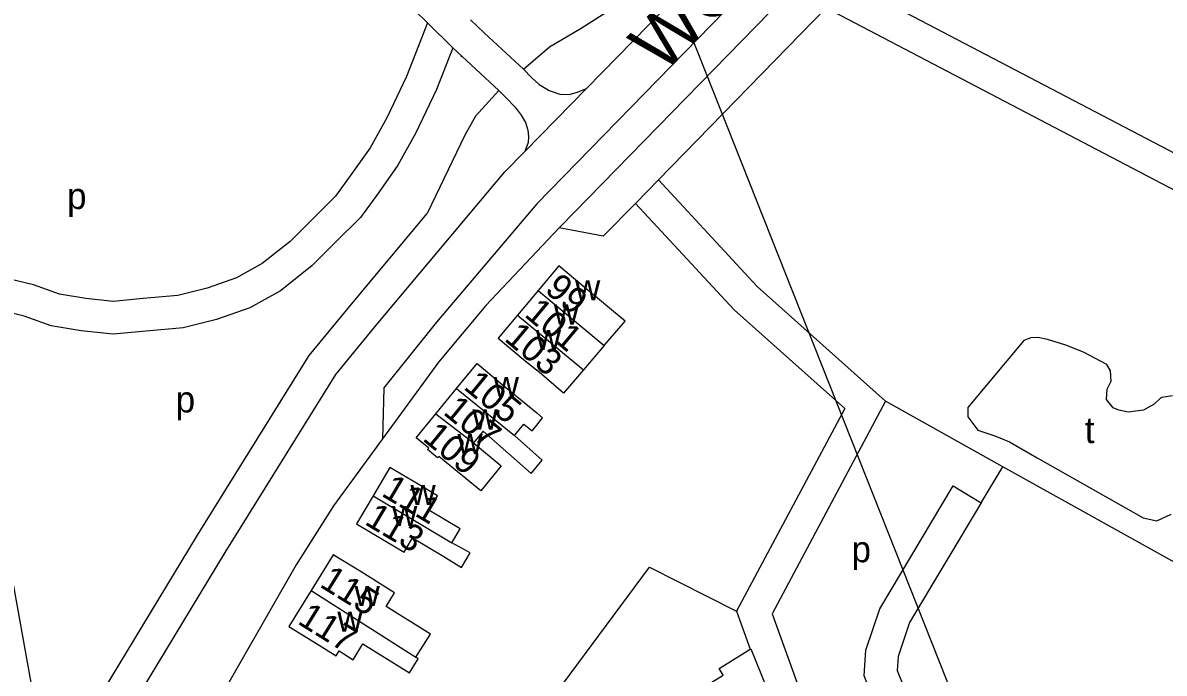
# Model space of a CAD drawing. Extents: x 162883 to 165538, y 383986 to 385172.
# Drawn here: x 164421.3 to 164596.1, y 384862.4 to 384962 of the extents above; entities that cross this region are included whole.
import ezdxf

# ---------------------------------------------------------------- set-up
doc = ezdxf.new("R2010")
doc.units = 0
for name, color, linetype in [('BLT_Basislijn', 7, 'Continuous'), ('BLT_Bebouwing', 7, 'Continuous'), ('BLT_Centroide', 7, 'Continuous'), ('BLT_Hoogspanningsmast_en_leidingen', 7, 'Continuous'), ('BLT_Huisnummer', 7, 'Continuous'), ('BLT_Huisnummer_ tussenligend', 7, 'Continuous'), ('BLT_Onderverdeling_panden', 7, 'Continuous'), ('BLT_Straatnaam_hoofdweg', 7, 'Continuous'), ('BLT_Vlakafsluiter', 7, 'Continuous')]:
    doc.layers.add(name, color=color, linetype=linetype)

msp = doc.modelspace()

# ---------------------------------------------------------------- linework, layer by layer
at = {"layer": 'BLT_Basislijn'}
for p, q in [((164589.79, 385026.4), (164500.03, 384934.28)), ((164578.81, 385007.97), (164503.61, 384930.79)), ((164548, 384968.08), (164658.3, 384910.3)), ((164544.36, 384964.34), (164518.64, 384937.96)), ((164544.36, 384964.34), (164663.27, 384902.05)), ((164491.99, 384960.42), (164497.99, 384954.91)), ((164487.17, 384958.19), (164494.22, 384951.67)), ((164518.64, 384937.96), (164515.14, 384934.37)), ((164503.46, 384930.63), (164492.22, 384918.72)), ((164503.61, 384930.79), (164503.46, 384930.63)), ((164571.42, 384894.04), (164553.46, 384904.05)), ((164568.11, 384888.51), (164571.42, 384894.04)), ((164622.91, 384865.35), (164571.42, 384894.04)), ((164530.6, 384871.89), (164532.71, 384866.07))]:
    msp.add_line(p, q, dxfattribs=at)
for points in [[(164507.61, 384951.95), (164526.58, 384971.35), (164580.15, 385026.28)], [(164458.77, 384969.91), (164466.55, 384971.29), (164470.08, 384971.61), (164472.32, 384971.29), (164474.57, 384970.16), (164477.3, 384967.91), (164483.29, 384962)], [(164497.99, 384954.91), (164501.95, 384958.33), (164506.81, 384961.21), (164515.23, 384966.64)], [(164483.29, 384962), (164480.07, 384953.82), (164477.02, 384947.49), (164474.49, 384942.87), (164471.7, 384938.93), (164469.19, 384935.5), (164465.49, 384931.79), (164462.23, 384928.54), (164457.95, 384925.16), (164454, 384922.96), (164449.51, 384921.39), (164445.02, 384920.26), (164439.68, 384919.8), (164435.13, 384919.34), (164430.9, 384919.79), (164426.87, 384920.46), (164422.89, 384921.87), (164418.02, 384923.08)], [(164483.29, 384962), (164487.17, 384958.19)], [(164489.87, 384962.5), (164491.99, 384960.42)], [(164487.17, 384958.19), (164484.66, 384951.82), (164481.47, 384945.2), (164478.73, 384940.22), (164475.76, 384936.01), (164473, 384932.23), (164469.02, 384928.26), (164465.56, 384924.8), (164460.73, 384920.98), (164456.05, 384918.38), (164450.95, 384916.59), (164445.85, 384915.32), (164440.15, 384914.82), (164435.11, 384914.32), (164430.23, 384914.83), (164425.62, 384915.6), (164421.45, 384917.07), (164416.73, 384918.25)], [(164488.38, 384956.99), (164488.51, 384956.86)], [(164497.99, 384954.91), (164499.22, 384953.63), (164500.37, 384952.59), (164501.9, 384951.66), (164503.54, 384951.12), (164504.96, 384951.06), (164506.27, 384951.39), (164507.61, 384951.95)], [(164494.22, 384951.67), (164490.62, 384947.71), (164489, 384944.83), (164483.24, 384932.8)], [(164494.22, 384951.67), (164495.34, 384950.52), (164496.71, 384949.1), (164497.64, 384947.89), (164498.29, 384946.74), (164498.62, 384945.6), (164498.73, 384944.61), (164498.67, 384943.68), (164498.17, 384942.31)], [(164495.12, 384939.19), (164498.17, 384942.31)], [(164430.45, 384844.87), (164452.27, 384880.91), (164469.23, 384908.15), (164475.48, 384915.75), (164495.12, 384939.19)], [(164518.64, 384937.96), (164533.76, 384921.62), (164553.46, 384904.05)], [(164500.03, 384934.28), (164484.63, 384916.19), (164476.59, 384906.14), (164476.36, 384898.29)], [(164515.14, 384934.37), (164510.16, 384929.34), (164503.46, 384930.63)], [(164515.14, 384934.37), (164530.26, 384918.05), (164547.2, 384902.94), (164530.6, 384871.89)], [(164425.24, 384845.92), (164448.01, 384883.53), (164465.16, 384911.08), (164471.63, 384918.94), (164483.24, 384932.8)], [(164492.22, 384918.72), (164484.96, 384910.04), (164476.36, 384898.29)], [(164597.41, 384904.91), (164595.78, 384904.65), (164595.6, 384904.54), (164594.59, 384903.61), (164594.59, 384903.61), (164592.95, 384902.68), (164590.61, 384902.37), (164590.61, 384902.37), (164589.21, 384902.67), (164588.35, 384903.06), (164587.29, 384904.35), (164587.39, 384905.92), (164588, 384907.16), (164587.93, 384908.72), (164587.34, 384909.67), (164583.77, 384911.57), (164581.05, 384912.65), (164578.25, 384913.54), (164576.8, 384913.85), (164575.69, 384913.75), (164574.64, 384913.37), (164566.04, 384903.12), (164566.06, 384901.67), (164567.58, 384899.62), (164570.18, 384898.78), (164572.44, 384897.87), (164576.66, 384895.41), (164592.93, 384886.19), (164595.01, 384885.74), (164597.21, 384886.74)], [(164425.24, 384845.92), (164413.97, 384908.4)], [(164553.46, 384904.05), (164536.06, 384871.5), (164544.74, 384847.47)], [(164476.36, 384898.29), (164468.85, 384888.02), (164463.15, 384879.01), (164441.34, 384840.94), (164434.48, 384829.48), (164428.37, 384816.83), (164421.19, 384799.97), (164416.17, 384784.39), (164411.44, 384762.47)], [(164558.83, 384840.61), (164550.16, 384861.98), (164550.41, 384865.93), (164552.56, 384872.27), (164563.82, 384891.08), (164568.11, 384888.51)], [(164568.11, 384888.51), (164557.12, 384870.16), (164555.36, 384864.96), (164555.22, 384862.8), (164563.47, 384842.49)], [(164449.13, 384779.73), (164443.92, 384782.89), (164466.3, 384814.08), (164499.55, 384854.74), (164517.27, 384878.66), (164530.6, 384871.89)]]:
    msp.add_lwpolyline(points, dxfattribs=at)
at = {"layer": 'BLT_Bebouwing'}
for p, q in [((164503.4, 384924.82), (164500.25, 384921.05)), ((164500.25, 384921.05), (164500, 384920.75)), ((164500, 384920.75), (164497.06, 384917.24)), ((164484.57, 384902.15), (164487.72, 384905.99)), ((164500.82, 384895.02), (164496.6, 384898.83)), ((164499.16, 384893), (164500.82, 384895.02))]:
    msp.add_line(p, q, dxfattribs=at)
for points in [[(164510.32, 384912.62), (164513.54, 384916.33), (164507.24, 384921.61), (164503.4, 384924.82)], [(164497.06, 384917.24), (164494.12, 384913.73), (164497.95, 384910.52), (164500, 384908.8)], [(164510.32, 384912.62), (164507.15, 384908.88)], [(164487.72, 384905.99), (164490.88, 384909.85), (164494.73, 384906.65), (164500, 384902.27)], [(164507.15, 384908.88), (164504.11, 384905.29), (164500, 384908.8)], [(164490.33, 384897.67), (164494.54, 384894.16), (164491.42, 384890.36), (164485, 384895.62), (164484.81, 384895.39), (164483.27, 384896.66), (164483.45, 384896.89), (164481.55, 384898.45), (164484.57, 384902.15)], [(164500, 384900.38), (164500.88, 384901.52), (164500, 384902.27)], [(164496.6, 384898.83), (164498.02, 384900.56), (164499.3, 384899.52), (164500, 384900.38)], [(164499.16, 384893), (164491.81, 384899.47), (164490.33, 384897.67)], [(164487.02, 384882.4), (164488.28, 384884.51), (164483.49, 384887.36), (164484.8, 384889.57), (164481.82, 384891.34), (164477.52, 384893.9), (164474.95, 384889.59)], [(164474.95, 384889.59), (164472.38, 384885.28), (164476.68, 384882.72), (164479.68, 384880.93), (164480.99, 384883.14), (164485.77, 384880.3), (164488.49, 384878.59), (164489.82, 384880.83), (164487.02, 384882.4)], [(164481.5, 384864.87), (164483.72, 384868.4), (164476.92, 384872.62), (164478.23, 384874.73), (164473.09, 384877.92), (164468.84, 384880.56), (164465.43, 384875.06)], [(164465.43, 384875.06), (164462.02, 384869.57), (164466.26, 384866.93), (164469.26, 384865.07), (164469.71, 384865.81), (164471.87, 384864.47), (164473.36, 384866.88), (164480.52, 384862.44), (164481.86, 384864.6), (164481.5, 384864.87)], [(164523.7, 384851.79), (164520.44, 384857.11), (164528.58, 384862.11), (164527.95, 384863.14), (164532.71, 384866.07)], [(164532.71, 384866.07), (164532.81, 384866.13), (164537.91, 384853.52)]]:
    msp.add_lwpolyline(points, dxfattribs=at)
at = {"layer": 'BLT_Hoogspanningsmast_en_leidingen'}
msp.add_line((164594.98, 384780.29), (164501.03, 385017.23), dxfattribs=at)
at = {"layer": 'BLT_Onderverdeling_panden'}
for p, q in [((164500.25, 384921.05), (164510.32, 384912.62)), ((164497.06, 384917.24), (164507.15, 384908.88)), ((164487.72, 384905.99), (164496.6, 384898.83)), ((164484.57, 384902.15), (164490.33, 384897.67)), ((164474.95, 384889.59), (164487.02, 384882.4)), ((164465.43, 384875.06), (164481.5, 384864.87))]:
    msp.add_line(p, q, dxfattribs=at)
at = {"layer": 'BLT_Vlakafsluiter'}
msp.add_line((164498.17, 384942.31), (164507.61, 384951.95), dxfattribs=at)

# ---------------------------------------------------------------- texts
at = {"layer": 'BLT_Centroide'}
for s, p in [('p', (164428.05, 384933.51)), ('w', (164505.88, 384919.53)), ('w', (164502.62, 384915.81)), ('w', (164499.86, 384911.89)), ('w', (164493.41, 384904.69)), ('p', (164444.69, 384902.35)), ('w', (164490.15, 384899.73)), ('t', (164583.98, 384897.65)), ('w', (164487.86, 384895.97)), ('w', (164480.66, 384888.16)), ('w', (164477.84, 384884.94)), ('p', (164548.24, 384879.4)), ('w', (164472.1, 384872.69)), ('w', (164469.46, 384868.75))]:
    msp.add_text(s, height=4, dxfattribs=at).set_placement(p)
at = {"layer": 'BLT_Huisnummer'}
for s, rotation, p in [('99', 320.0696, (164501.07, 384920.9)), ('103', 320.0697, (164494.87, 384913.46)), ('105', 320.6509, (164488.62, 384906.06)), ('109', 320.6491, (164482.36, 384898.16)), ('111', 329.2083, (164476.04, 384889.66)), ('113', 329.2165, (164473.46, 384885.31)), ('115', 328.1842, (164466.57, 384875.75)), ('117', 328.1793, (164463.19, 384870.08))]:
    msp.add_text(s, height=4, rotation=rotation, dxfattribs=at).set_placement(p)
at = {"layer": 'BLT_Huisnummer_ tussenligend'}
for s, rotation, p in [('101', 320.0696, (164497.95, 384917.16)), ('107', 320.6509, (164485.51, 384902.19))]:
    msp.add_text(s, height=4, rotation=rotation, dxfattribs=at).set_placement(p)
at = {"layer": 'BLT_Straatnaam_hoofdweg'}
msp.add_text('WOLVENDIJK', height=8, rotation=45.0108, dxfattribs=at).set_placement((164519.27, 384954.07))

doc.saveas('drawing.dxf')
